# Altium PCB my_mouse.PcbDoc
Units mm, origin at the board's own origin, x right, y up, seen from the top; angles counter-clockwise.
Board outline 49.33 x 40 mm, 2 copper layers (Top Layer, Bottom Layer); 26 components, 28 nets, 111 pads, 26 vias.
Unrouted connection lines stored in the file: 21.
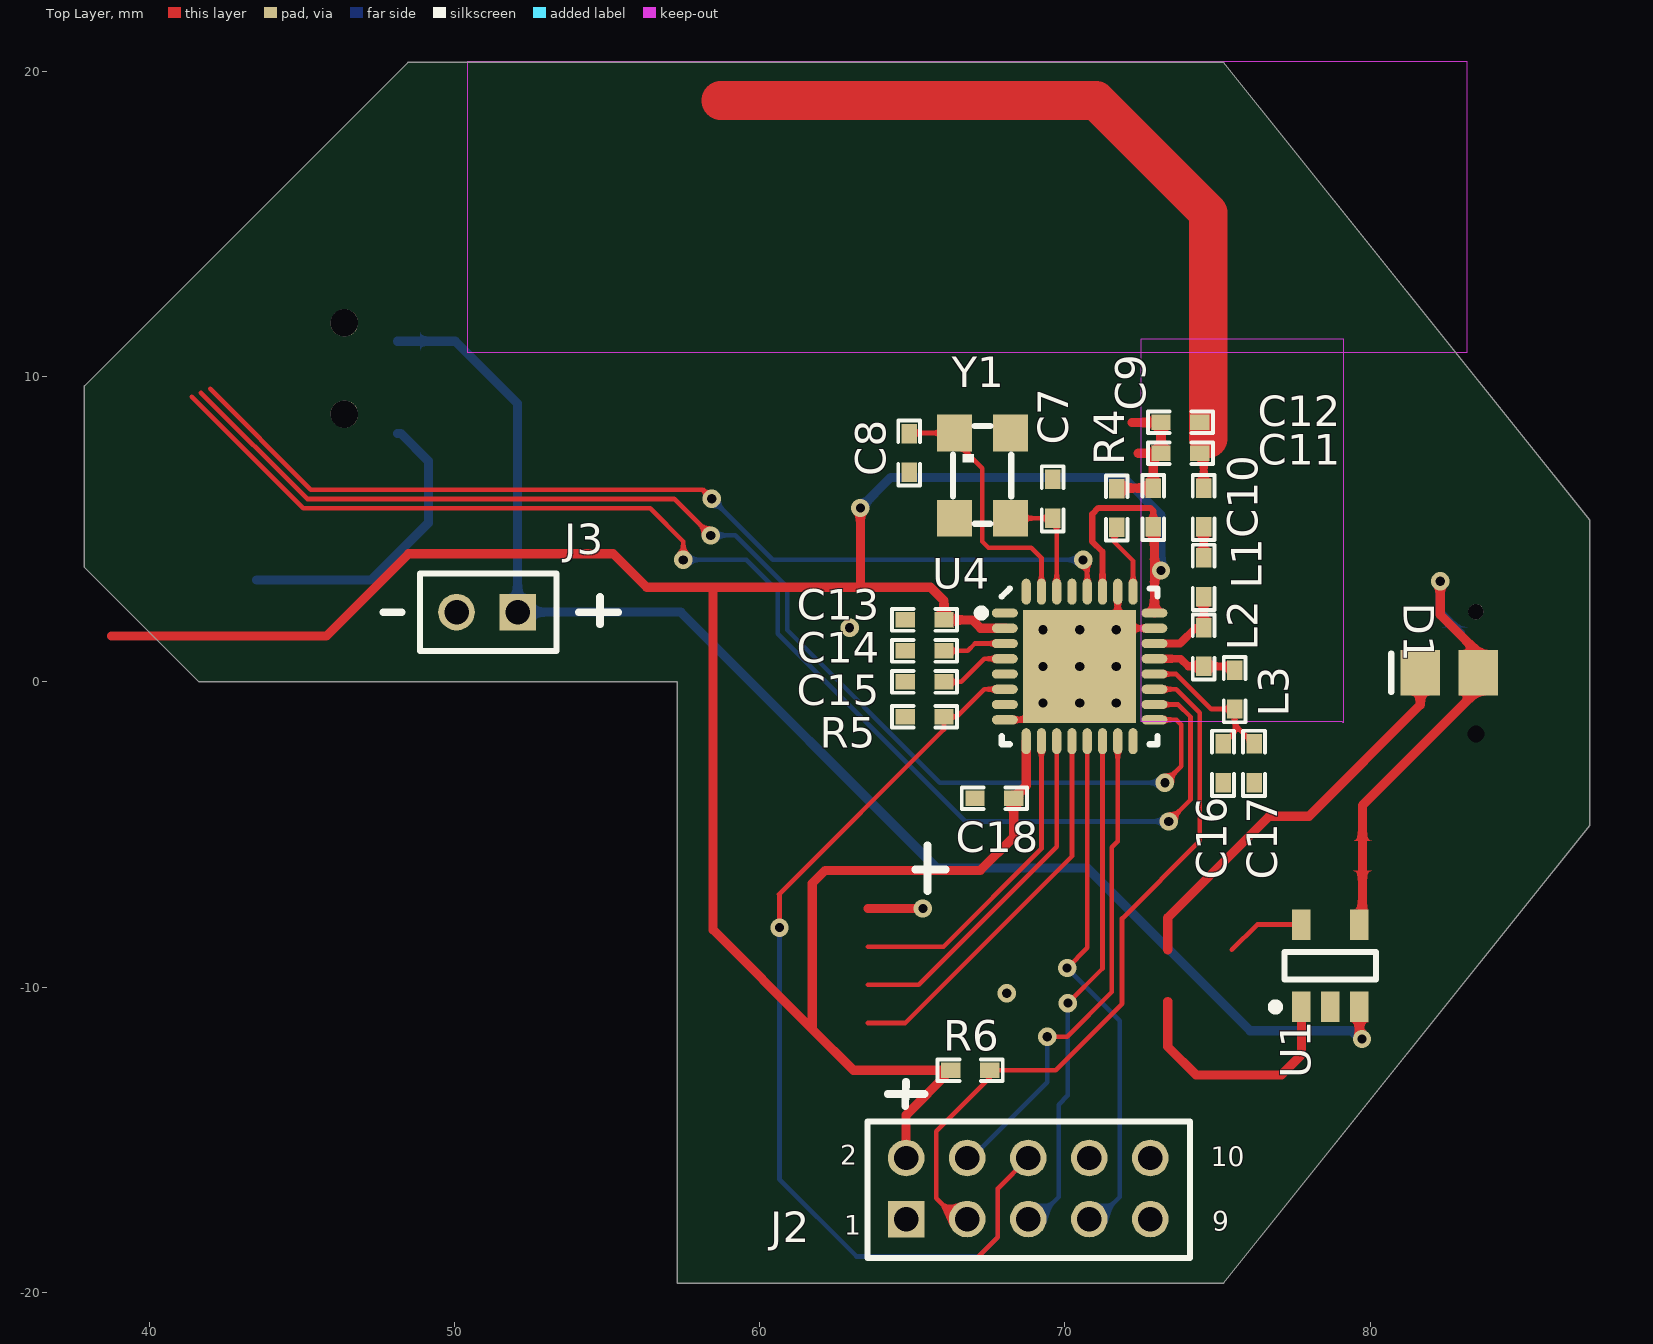
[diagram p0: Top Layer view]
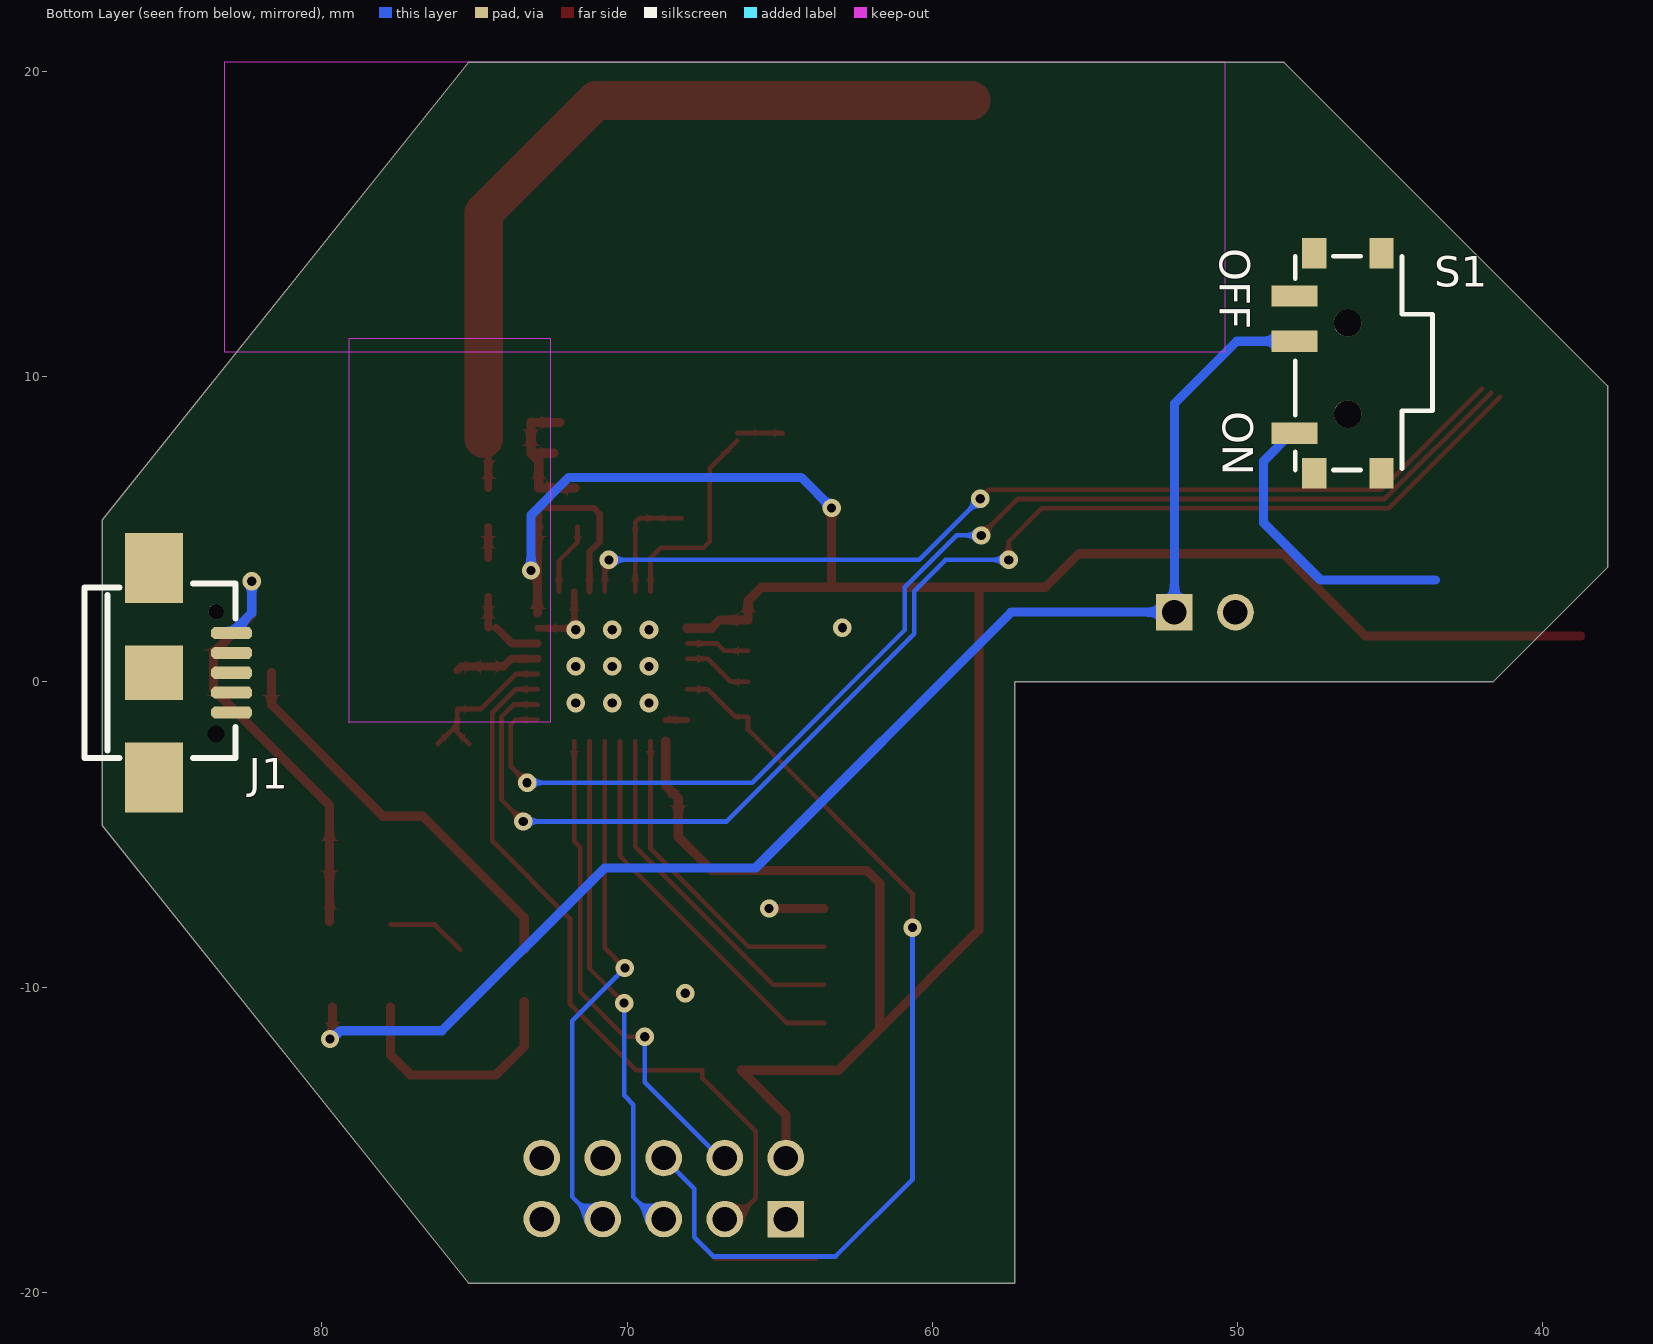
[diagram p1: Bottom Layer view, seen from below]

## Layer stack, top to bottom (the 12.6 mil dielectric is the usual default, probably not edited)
Top Solder: solder mask 0.0102, Solder Resist, Dk 3.5
Top Layer: signal copper 0.0356
Dielectric 1: dielectric 0.32, FR-4, Dk 4.8
Bottom Layer: signal copper 0.0356
Bottom Solder: solder mask 0.0102, Solder Resist, Dk 3.5

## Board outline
37.875,3.752 41.627,0 57.3,0 57.3,-19.7 75.2,-19.7 87.2,-4.7 87.2,5.3 75.2,20.3 48.475,20.3 37.875,9.7

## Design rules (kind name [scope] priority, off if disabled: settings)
Clearance Clearance_1 [InPolygon] p1: gap=0.254
Clearance [All] p2: gap=0.152
ComponentClearance [All] p1: gap=0.1 collisioncheckmode=3 verticalgap=2540 showdistances=FALSE
HoleToHoleClearance [All] p1: gap=0.1 allowstackedmicrovias=TRUE
MinimumSolderMaskSliver [All] p1: minsoldermaskwidth=0.1
PolygonConnect [All] p1: connectstyle=Relief reliefconductorwidth=0.254 reliefentries=4 polygonreliefangle="90 Angle" airgapwidth=0.254
RoutingVias [All] p1: holewidth=0.4 width=0.8 viastyle="Through Hole" minholewidth=0.3 minwidth=0.6 maxholewidth=0.4 maxwidth=0.8
SilkToSilkClearance [All] p1: silktosilkclearance=0.1
SilkToSolderMaskClearance [IsPad] p1: minsilkscreentomaskgap=0 clearancetoexposedcopper=TRUE
SolderMaskExpansion [All] p1: expansion=0.102
UnpouredPolygon [All] p1: allowunpoured=FALSE
Width [All] p1: maxlimit=1.27 minlimit=0.15 preferedwidth=0.2
24 further rules are at their usual default settings.

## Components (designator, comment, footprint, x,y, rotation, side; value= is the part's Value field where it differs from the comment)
C7 "Cap-S" 0402s 69.6,6 r90 top
C8 "Cap-S" 0402s 64.9,7.5 r90 top
C9 "Cap-S" 0402s 72.898,5.715 r270 top
C10 "Cap-S" 0402s 74.549,5.715 r270 top
C11 "Cap-S" 0402s 73.787,7.493 r180 top
C12 "Cap-S" 0402s 73.787,8.509 r180 top
C13 "X7R 16V" 0402s 65.405,2.032 r0 top
C14 "X7R 16V" 0402s 65.405,1.016 r0 top
C15 "X7R 16V" 0402s 65.405,0 r0 top
C16 "Cap-S" 0402s 75.184,-2.667 r90 top
C17 "Cap-S" 0402s 76.2,-2.667 r90 top
C18 "Cap-S" 0402s 67.691,-3.81 r0 top
D1 "LED0" LED-0805 82.6,0.3 r180 top
J1 "USB_M" USB_MICRO 85.5,0.3 r270 bottom
J2 "Header 5X2" HEAD2X5_0.2 64.8,-17.6 r0 top
J3 "Header 2" head2_2.0 52.07,2.286 r180 top
L1 "Inductor" 0402s 74.549,3.429 r90 top
L2 "Inductor" 0402s 74.549,1.143 r90 top
L3 "Inductor" 0402s 75.565,-0.254 r270 top
R4 "Res1" 0402s 71.7,5.7 r90 top
R5 "Res1" 0402s 65.405,-1.143 r0 top
R6 "Res1" 0402s 66.9,-12.725 r0 top
S1 "SW-SPDT" 三脚拨动开关2 46.394,11.764 r270 bottom
U1 "SGM4054" SGM4054 78.7,-9.3 r90 top
U4 "NRF24LE1" Nordic_QFN50P500X500X90-33N 70.485,0.508 r0 top
Y1 "CRYSTAL-4-P" OSC3225 67.437,6.858 r90 top

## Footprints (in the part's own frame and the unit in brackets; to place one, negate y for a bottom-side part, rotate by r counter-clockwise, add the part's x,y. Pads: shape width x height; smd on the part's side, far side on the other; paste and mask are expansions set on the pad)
0402s [mil]
  rect 25x20 smd: 1(-25,0) 2(25,0)
  silkscreen extent -42,-14 42,14
head2_2.0 [mm]
  rect 1.2x1.2 hole 0.8: 1(0,0)
  round 1.2 hole 0.8: 2(2,0)
  silkscreen extent -3.3,-1.27 4.4,1.27
HEAD2X5_0.2 [mm]
  rect 1.2x1.2 hole 0.8: 1(0,0)
  round 1.2 hole 0.8: 2(0,2) 3(2,0) 4(2,2) 5(4,0) 6(4,2) 7(6,0) 8(6,2) 9(8,0) 10(8,2)
  silkscreen extent -1.27,-1.27 9.3,3.2
LED-0805 [mm] "贴片LED"
  rect 1.3x1.5 smd: 1(-0.95,0) 2(0.95,0)
  silkscreen extent 1.91,-0.63 1.91,0.64
Nordic_QFN50P500X500X90-33N [mm] "QFN32 5x5x0.85mm, 0.5mm pitch - Medium Density"
  oval 0.85x0.3 smd mask+0.076: 1(-2.45,1.75) 2(-2.45,1.25) 3(-2.45,0.75) 4(-2.45,0.25) 5(-2.45,-0.25) 6(-2.45,-0.75) 7(-2.45,-1.25) 8(-2.45,-1.75) 17(2.45,-1.75) 18(2.45,-1.25) 19(2.45,-0.75) 20(2.45,-0.25) 21(2.45,0.25) 22(2.45,0.75) 23(2.45,1.25) 24(2.45,1.75)
  oval 0.3x0.85 smd mask+0.076: 9(-1.75,-2.45) 10(-1.25,-2.45) 11(-0.75,-2.45) 12(-0.25,-2.45) 13(0.25,-2.45) 14(0.75,-2.45) 15(1.25,-2.45) 16(1.75,-2.45) 25(1.75,2.45) 26(1.25,2.45) 27(0.75,2.45) 28(0.25,2.45) 29(-0.25,2.45) 30(-0.75,2.45) 31(-1.25,2.45) 32(-1.75,2.45)
  rect 3.7x3.7 smd mask+0: 33(0,0)
  silkscreen extent -3.34,-2.55 2.55,2.55
OSC3225 [mm]
  rect 1.2x1.143 smd: 1(1.298,1.047) 2(-1.496,1.047) 3(-1.496,-0.782) 4(1.298,-0.782)
  silkscreen extent -1.67,-0.81 1.53,1.1
SGM4054 [mm]
  rect 1x0.6 smd: 1(-1.35,0.95) 2(-1.35,0) 3(-1.35,-0.95) 4(1.35,-0.95) 5(1.35,0.95)
  silkscreen extent -1.47,-1.5 0.45,1.92, body extent -0.85,-1.5 0.85,1.5, height 0.9
USB_MICRO [mm] "USB方孔"
  round 0.5 hole 0.5: 0(-2,2.032)
  round 0.5 hole 0.56: 0(2,2.032)
  oct 0.4x1.35 smd: 1(-1.3,2.54) 2(-0.65,2.54) 3(0,2.54) 4(0.65,2.54) 5(1.3,2.54)
  rect 2.286x1.9 smd: 6(3.429,0) 7(-3.429,0)
  rect 1.8x1.9 smd: 8(0,0)
  silkscreen extent -2.92,-2.29 2.79,2.67
三脚拨动开关2 [mm]
  rect 0.7x1.5 smd: 1(3.62,-1.745) 2(0.6,-1.745) 3(-0.88,-1.745)
  rect 1x0.8 smd: ""(-2.28,-1.09) ""(-2.28,1.11) ""(4.92,-1.09) ""(4.92,1.11)
  round 0.9 hole 0.9: ""(0,0) ""(2.99,0)
  silkscreen extent -2.18,-1.72 4.82,2.78

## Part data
C7 C8 C9 C10 C11 C12 C16 C17 C18: "贴片瓷片电容"
C13 C14 C15: library part Cap, "Capacitor"
D1: "发光二极管"
J1: "Micro/Mini USB"
J2: "Header, 5-Pin, Dual row"
J3: "Header, 2-Pin"
R4 R5 R6: "贴片电阻"
S1: "开关"

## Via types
v1: diameter 0.6, hole 0.3, Top Layer to Bottom Layer, 17 vias
v2: diameter 0.61, hole 0.305, Top Layer to Bottom Layer, tented top, 9 vias

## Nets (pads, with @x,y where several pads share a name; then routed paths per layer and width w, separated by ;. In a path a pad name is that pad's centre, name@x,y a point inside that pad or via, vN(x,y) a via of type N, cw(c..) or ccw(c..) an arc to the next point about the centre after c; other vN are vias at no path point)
ANTENNA: C10.1 C11.1 C12.1 | length 25.9
  Top Layer w0.254: C10.1 C11.1@74.549,7.366
  Top Layer w1.27: 58.725,19.053 71.018,19.053 74.701,15.37 74.701,7.979
BAT4.2: J3.1 S1.2 U1.3 | length 46
  Top Layer w0.3: v1@79.65,-11.61 U1.3
  Bottom Layer w0.3: S1.2 50.026,11.164 52.07,9.12 J3.1 57.414,2.286 65.796,-6.096 70.739,-6.096 76.073,-11.43 79.4,-11.43 79.67,-11.7 v1(79.74,-11.7)
CHRG: U1.1 | length 8.1
  Top Layer w0.3: 73.375,-10.475 73.375,-11.95 74.3,-12.875 77.1,-12.875 77.75,-12.225 U1.1
GND: C7.2 C8.1 C9.1 C11.2 C12.2 C13.1 C14.1 C15.1 C16.1 C17.1 C18.1 J1.4 J1.5 J2.10 J3.2 R4.2 R5.1 U1.2 U4.8 U4.23 U4.26 Y1.2 Y1.4 | length 8.2
  Top Layer w0.2: U4.8 68.735,-1.242 ; U4.26 71.735,1.758 U4.23
  Top Layer w0.3: R4.2@71.715,6.35 C9.1 72.898,7.239 C11.2 ; 72.2,8.5 73.143,8.5 C12.2 C11.2 ; 72.407,7.493 C11.2
  other v1: 68.1,-10.2 62.95,1.775
MOTSWK: U4.17 | length 40.8
  Top Layer w0.152: 41.695,9.474 45.174,5.995 57.205,5.995 v1(58.4,4.8) ; U4.17 73.657,-1.242 73.812,-1.397 73.812,-2.769 v1(73.279,-3.302)
  Bottom Layer w0.152: v1(58.4,4.8) 59.2,4.8 60.9,3.1 60.9,1.7 65.902,-3.302 v1(73.279,-3.302)
NetC7_1: C7.1 U4.30 Y1.3 | length 3.8
  Top Layer w0.152: Y1.3 69.597,5.362 C7.1 69.735,5.23 U4.30
NetC8_2: C8.2 U4.31 Y1.1 | length 8.4
  Top Layer w0.152: C8.2 64.921,8.156 Y1.1 ; Y1.1@66.39,7.91 67.3,7 67.3,4.6 67.5,4.4 68.9,4.4 69.235,4.065 U4.31
NetC10_2: C10.2 L1.2 | length 1
  Top Layer w0.254: L1.2 C10.2
NetC14_2: C14.2 U4.3 | length 2.1
  Top Layer w0.152: C14.2 66.816,1.016 67.058,1.258 U4.3
NetC15_2: C15.2 U4.4 | length 2.3
  Top Layer w0.152: C15.2 66.6,0 67.358,0.758 U4.4
NetC16_2: C16.2 C17.2 L3.2 U4.20 | length 5.3
  Top Layer w0.152: U4.20 73.656,0.258 74.803,-0.889 L3.2 75.565,-1.397 ; C16.2 75.565,-1.651 75.565,-1.397 ; C17.2 75.565,-1.397
NetD1_2: D1.2 | length 13.3
  Top Layer w0.3: 73.375,-8.775 73.375,-7.725 76.7,-4.4 78,-4.4 81.65,-0.75 D1.2
NetL1_1: L1.1 L2.2 U4.22 | length 2.6
  Top Layer w0.254: U4.22 73.775,1.258 74.295,1.778 ; L2.2 L1.1
NetL2_1: L2.1 L3.1 U4.21 | length 2.8
  Top Layer w0.254: U4.21 73.791,0.758 74.041,0.508 L2.1 75.438,0.508 L3.1
NetR4_1: R4.1 U4.25 | length 2.4
  Top Layer w0.152: R4.1@71.628,5.08 71.628,4.572 72.235,3.965 U4.25
NRF_MISO: J2.5 U4.14 | length 17
  Top Layer w0.152: v1(70.1,-10.525) 71.235,-9.39 U4.14
  Bottom Layer w0.152: J2.5@68.77,-17.907 69.8,-16.877 69.8,-13.85 70.1,-13.55 v1(70.1,-10.525)
NRF_MOSI: J2.7 U4.13 | length 17.4
  Top Layer w0.152: v1(70.075,-9.375) 70.735,-8.715 U4.13
  Bottom Layer w0.152: v1(70.075,-9.375) 71.8,-11.1 71.8,-16.877 J2.7@70.77,-17.907
NRF_NSS: J2.4 U4.15 | length 16.5
  Top Layer w0.152: v1(69.425,-11.625) 70.075,-11.625 71.54,-10.16 71.54,-5.422 71.735,-5.227 U4.15
  Bottom Layer w0.152: J2.4@66.77,-15.907 66.7,-15.837 69.425,-13.112 v1(69.425,-11.625)
NRF_PROG: J2.6 R5.2 U4.6 | length 38.5
  Top Layer w0.152: 60.637,-6.963 66.04,-1.56 R5.2 66.457,-1.143 67.358,-0.242 U4.6 ; v1(60.65,-8.05) 60.65,-6.975 ; 63.825,-18.9 67.1,-18.9 67.8,-18.2 67.8,-16.6 J2.6
  Bottom Layer w0.152: v1(60.65,-8.05) 60.65,-16.3 63.175,-18.825 67.175,-18.825 67.8,-18.2 67.8,-16.6 J2.6
NRF_RST: J2.3 R6.2 U4.19 | length 24
  Top Layer w0.152: J2.3@66.77,-17.907 65.786,-16.923 65.786,-14.725 67.535,-12.976 R6.2 69.698,-12.725 71.875,-10.548 71.875,-7.754 74.422,-5.207 74.422,-1.016 73.648,-0.242 U4.19
NRF_SCK/T_SDA: J2.8 U4.11 | length 11.5
  Top Layer w0.152: 63.55,-9.925 65.21,-9.925 69.735,-5.4 U4.11
PROG: U1.5 | length 2.6
  Top Layer w0.152: 75.475,-8.775 76.3,-7.95 U1.5
SCLK: U4.18 | length 44
  Top Layer w0.152: 41.39,9.347 45.047,5.69 56.41,5.69 57.5,4.6 v1(57.5,4) ; U4.18 73.717,-0.742 74.117,-1.142 74.117,-3.861 v1(73.406,-4.572)
  Bottom Layer w0.152: v1(57.5,4) 59.569,4 60.595,2.974 60.595,1.574 66.741,-4.572 v1(73.406,-4.572)
SDIO: U4.28 | length 32
  Top Layer w0.152: 42,9.6 45.3,6.3 58.131,6.3 v1(58.431,6) ; v1(70.6,4) 70.735,3.865 U4.28
  Bottom Layer w0.152: v1(58.431,6) 60.431,4 v1(70.6,4)
T_INT: U4.12 | length 12.7
  Top Layer w0.152: 63.55,-11.175 64.775,-11.175 70.235,-5.715 U4.12
T_SCL: U4.10 | length 10.5
  Top Layer w0.152: 63.55,-8.675 66.025,-8.675 69.235,-5.465 U4.10
USB_5V: D1.1 J1.1 U1.4 | length 15.2
  Top Layer w0.3: U1.4@79.75,-7.85 79.75,-5.7 79.75,-4.05 83.55,-0.25 D1.1 83.55,0.95 82.3,2.2 v1(82.3,3.3)
  Bottom Layer w0.3: v1(82.3,3.3) 82.3,2.26 J1.1
VCC_3.3V: C9.2 C13.2 C18.2 J2.2 R6.1 U4.2 U4.9 U4.24 U4.27 | length 95
  Top Layer w0.2: U4.27 71.235,4.265 70.9,4.6 70.9,5.5 71.1,5.7 72.8,5.7 72.898,5.602 C9.2
  Top Layer w0.3: 38.768,1.5 45.8,1.5 48.5,4.2 55.2,4.2 56.3,3.1 58.475,3.1 ; v1(63.3,5.7) 63.3,3.1 ; J2.2 64.8,-14.19 R6.1 63.075,-12.725 61.725,-11.375 ; U4.2 67.242,1.758 66.968,2.032 C13.2 66.04,2.66 65.6,3.1 63.3,3.1 ; U4.9 68.735,-3.401 C18.2 68.326,-5.08 67.231,-6.175 63.55,-6.175 62.15,-6.175 61.725,-6.6 61.725,-11.375 ; C9.2 72.935,5.043 v1@72.935,3.651 ; U4.24 v1@72.935,3.651 ; v1(73.151,3.651) v1@72.935,3.651 ; 58.475,3.1 58.475,-8.125 61.725,-11.375 ; 58.475,3.1 63.3,3.1
  Bottom Layer w0.3: v1(63.3,5.7) 64.3,6.7 71.913,6.7 73.151,5.463 v1(73.151,3.651)
pads on no net: J1.0 J1.2 J1.3 J1.6 J1.7 J1.8 J2.1 J2.9 S1. S1.1 S1.3 U4.1 U4.5 U4.7 U4.16 U4.29 U4.32 U4.33
copper on no net: | length 11.6
  Top Layer w0.3: 63.55,-7.425 v1(65.35,-7.425)
  Bottom Layer w0.3: 43.522,3.341 47.283,3.341 49.149,5.207 49.149,7.239 48.244,8.144 48.139,8.144
  other v2: 69.285,-0.692 70.485,-0.692 71.685,-0.692 69.285,0.508 70.485,0.508 71.685,0.508 69.285,1.708 70.485,1.708 71.685,1.708

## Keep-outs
Keep-Out Layer:
  pour cut-out: 50.419,20.32 50.419,10.795 83.185,10.795 83.185,20.32
  pour cut-out: 72.5,11.239 79.121,11.239 79.121,-1.333 79.087,-1.3 72.5,-1.3

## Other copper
Bottom Layer:
  pour cut-out: 81.6,1.4 81.6,-0.2 84.3,-0.2 84.3,1.4

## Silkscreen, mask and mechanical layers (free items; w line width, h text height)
Top Overlay:
  lines w0.254: 64.2,-13.5 65.4,-13.5 ; 64.77,-13.9 64.8,-13.1 ; 65.1,-6.15 66.1,-6.15 ; 65.5,-6.85 65.5,-5.35
Mechanical 1:
  the board outline again, w0.013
